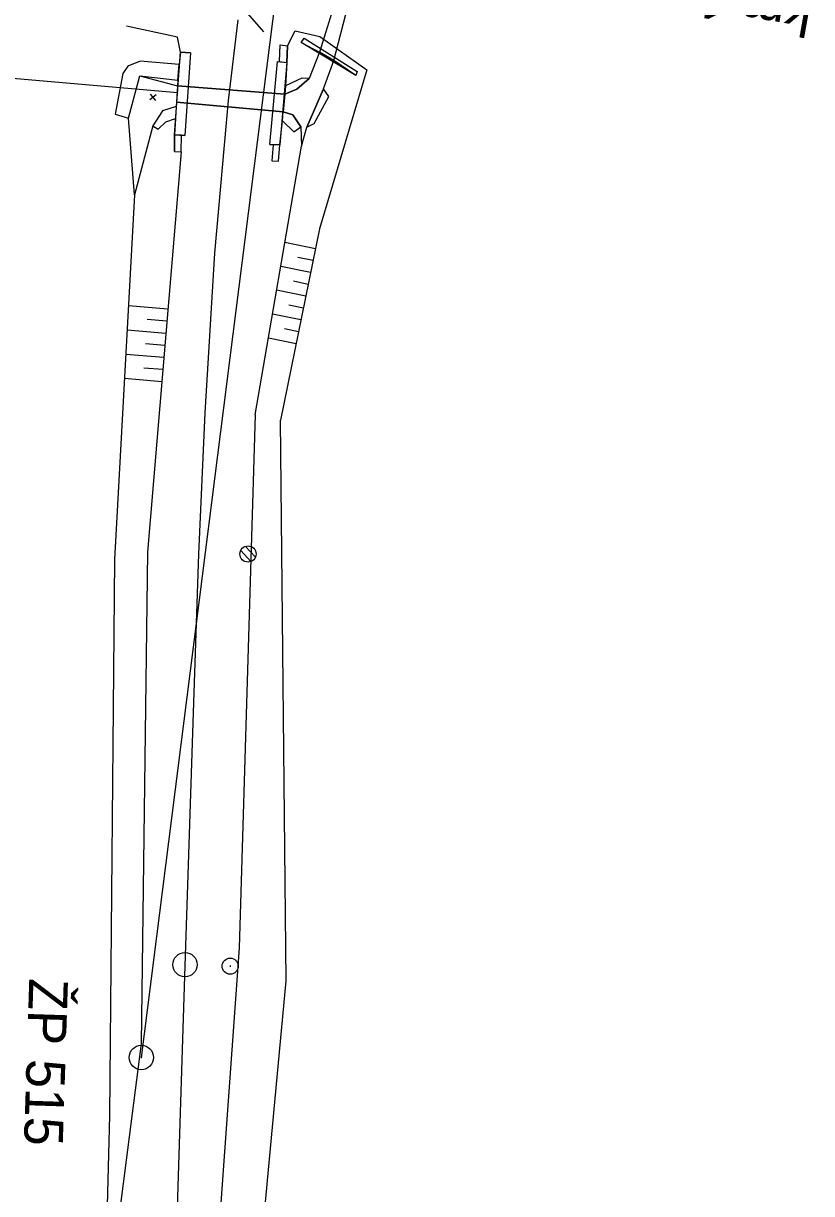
# Model space of a CAD drawing. Extents: x -738085 to -734426, y -1122197 to -1119748.
# Drawn here: x -735485.3 to -735436.6, y -1120600.6 to -1120528.2 of the extents above; entities that cross this region are included whole.
import ezdxf

# ---------------------------------------------------------------- set-up
doc = ezdxf.new("R2010")
doc.units = 0
for name, color, linetype in [('Vrstva 1', 7, 'Continuous'), ('Vrstva 11', 7, 'Continuous'), ('Vrstva 13', 7, 'Continuous'), ('Vrstva 19', 7, 'Continuous'), ('Vrstva 4', 7, 'Continuous'), ('Vrstva 48', 7, 'Continuous'), ('Vrstva 49', 7, 'Continuous'), ('Vrstva 63', 7, 'Continuous'), ('Vrstva 7', 7, 'Continuous'), ('Vrstva 9', 7, 'Continuous')]:
    doc.layers.add(name, color=color, linetype=linetype)

msp = doc.modelspace()

# ---------------------------------------------------------------- linework, layer by layer
at = {"layer": 'Vrstva 1'}
msp.add_lwpolyline([(-735472.033, -1120528.022), (-735472.637, -1120533.02), (-735473.481, -1120542.452), (-735474.077, -1120552.339), (-735474.468, -1120561.086), (-735474.782, -1120570.257), (-735475.334, -1120587.192), (-735475.897, -1120604.742)], dxfattribs=at)
msp.add_lwpolyline([(-735472.033, -1120528.022), (-735472.637, -1120533.02), (-735473.481, -1120542.452), (-735474.077, -1120552.339), (-735474.468, -1120561.086), (-735474.782, -1120570.257), (-735475.334, -1120587.192), (-735475.897, -1120604.742)], dxfattribs=at)
at = {"layer": 'Vrstva 11'}
for p, q in [((-735471.857, -1120560.849), (-735471.231, -1120561.533)), ((-735471.575, -1120560.601), (-735470.959, -1120561.275))]:
    msp.add_line(p, q, dxfattribs=at)
msp.add_circle((-735471.412, -1120561.07), 0.5, dxfattribs=at)
at = {"layer": 'Vrstva 13'}
for p, q in [((-735469.456, -1120530.61), (-735469.01, -1120530.674)), ((-735469.456, -1120530.61), (-735469.01, -1120530.674)), ((-735469.139, -1120532.633), (-735469.091, -1120532.115)), ((-735475.853, -1120533.392), (-735475.904, -1120534.129)), ((-735469.276, -1120534.274), (-735469.241, -1120533.724)), ((-735475.963, -1120536.178), (-735475.551, -1120536.186)), ((-735469.449, -1120535.765), (-735469.449, -1120535.765)), ((-735469.535, -1120536.761), (-735469.535, -1120536.761))]:
    msp.add_line(p, q, dxfattribs=at)
for points in [[(-735469.456, -1120530.61), (-735469.421, -1120529.58), (-735468.968, -1120529.627), (-735469.01, -1120530.674)], [(-735469.01, -1120530.674), (-735469.01, -1120530.674), (-735468.968, -1120529.627)], [(-735475.668, -1120530.787), (-735478.074, -1120530.581), (-735478.838, -1120530.892), (-735479.156, -1120531.352), (-735479.624, -1120533.867), (-735478.811, -1120534.119), (-735478.105, -1120531.488), (-735475.752, -1120531.75), (-735475.668, -1120530.787)], [(-735469.139, -1120532.633), (-735468.384, -1120532.305), (-735467.64, -1120531.662), (-735468.091, -1120531.635), (-735469.091, -1120532.115)], [(-735466.736, -1120532.288), (-735467.783, -1120534.657), (-735467.328, -1120534.443), (-735466.42, -1120532.761), (-735466.736, -1120532.288)], [(-735475.853, -1120533.392), (-735476.707, -1120533.65), (-735477.299, -1120534.592), (-735476.972, -1120534.792), (-735476.496, -1120534.327), (-735475.904, -1120534.129)], [(-735469.276, -1120534.274), (-735468.579, -1120534.96), (-735468.149, -1120534.642), (-735468.648, -1120533.901), (-735469.241, -1120533.724)], [(-735475.516, -1120535.164), (-735475.963, -1120535.13), (-735475.963, -1120536.178), (-735475.551, -1120536.186), (-735475.516, -1120535.164)], [(-735475.963, -1120536.178), (-735475.963, -1120536.178), (-735475.963, -1120535.13), (-735475.963, -1120535.13)], [(-735469.849, -1120535.753), (-735469.935, -1120536.75), (-735469.535, -1120536.761), (-735469.449, -1120535.765), (-735469.849, -1120535.753)], [(-735469.935, -1120536.75), (-735469.535, -1120536.761), (-735469.449, -1120535.765)]]:
    msp.add_lwpolyline(points, dxfattribs=at)
at = {"layer": 'Vrstva 19'}
for p, q in [((-735461.122, -1120511.205), (-735466.99, -1120530.023)), ((-735466.103, -1120530.55), (-735461.122, -1120511.205)), ((-735475.771, -1120532.55), (-735515.222, -1120529.126)), ((-735468.122, -1120529.424), (-735466.99, -1120530.023)), ((-735464.735, -1120531.469), (-735466.103, -1120530.55)), ((-735469.139, -1120532.633), (-735475.773, -1120532.099)), ((-735475.773, -1120532.099), (-735469.139, -1120532.633)), ((-735475.837, -1120533.127), (-735469.241, -1120533.724)), ((-735469.241, -1120533.724), (-735475.837, -1120533.127)), ((-735475.963, -1120535.13), (-735475.313, -1120535.18))]:
    msp.add_line(p, q, dxfattribs=at)
for points in [[(-735468.122, -1120529.424), (-735467.934, -1120529.164), (-735464.66, -1120531.219), (-735464.735, -1120531.469), (-735468.122, -1120529.424)], [(-735475.313, -1120535.18), (-735475.963, -1120535.13), (-735475.583, -1120530.02), (-735474.968, -1120530.061), (-735475.313, -1120535.18)], [(-735475.313, -1120535.18), (-735475.963, -1120535.13), (-735475.583, -1120530.02), (-735474.968, -1120530.061), (-735475.313, -1120535.18)], [(-735475.583, -1120530.02), (-735475.668, -1120530.787), (-735475.752, -1120531.75)], [(-735474.968, -1120530.061), (-735475.583, -1120530.02), (-735475.583, -1120530.02)], [(-735474.968, -1120530.061), (-735474.968, -1120530.061), (-735475.313, -1120535.18), (-735475.313, -1120535.18)], [(-735466.99, -1120530.023), (-735466.99, -1120530.023), (-735466.103, -1120530.55), (-735466.103, -1120530.55)], [(-735469.595, -1120530.603), (-735469.01, -1120530.674), (-735469.449, -1120535.765), (-735470.068, -1120535.747), (-735469.595, -1120530.603)], [(-735470.068, -1120535.747), (-735470.068, -1120535.747), (-735469.595, -1120530.603), (-735469.595, -1120530.603)], [(-735469.595, -1120530.603), (-735469.01, -1120530.674), (-735469.01, -1120530.674)], [(-735469.01, -1120530.674), (-735469.091, -1120532.115), (-735469.139, -1120532.633)], [(-735469.01, -1120530.674), (-735469.091, -1120532.115), (-735469.139, -1120532.633)], [(-735475.752, -1120531.75), (-735475.773, -1120532.099), (-735475.773, -1120532.099), (-735475.837, -1120533.127), (-735475.837, -1120533.127), (-735475.853, -1120533.392)], [(-735469.241, -1120533.724), (-735469.241, -1120533.724), (-735469.139, -1120532.633), (-735469.139, -1120532.633)], [(-735475.853, -1120533.392), (-735475.904, -1120534.129), (-735475.963, -1120535.13), (-735475.963, -1120535.13)], [(-735469.449, -1120535.765), (-735469.276, -1120534.274), (-735469.241, -1120533.724)], [(-735470.068, -1120535.747), (-735469.449, -1120535.765), (-735469.449, -1120535.765)]]:
    msp.add_lwpolyline(points, dxfattribs=at)
at = {"layer": 'Vrstva 4'}
msp.add_line((-735473.474, -1120525.286), (-735470.457, -1120528.771), dxfattribs=at)
at = {"layer": 'Vrstva 48'}
for p, q in [((-735467.238, -1120542.185), (-735469.129, -1120541.797)), ((-735467.388, -1120542.919), (-735468.322, -1120542.728)), ((-735467.538, -1120543.654), (-735469.385, -1120543.276)), ((-735467.689, -1120544.389), (-735468.601, -1120544.202)), ((-735467.839, -1120545.124), (-735469.641, -1120544.755)), ((-735476.371, -1120545.927), (-735478.808, -1120545.722)), ((-735467.99, -1120545.858), (-735468.879, -1120545.676)), ((-735468.14, -1120546.593), (-735469.897, -1120546.234)), ((-735476.434, -1120546.675), (-735477.642, -1120546.573)), ((-735468.29, -1120547.328), (-735469.158, -1120547.15)), ((-735476.497, -1120547.422), (-735478.891, -1120547.221)), ((-735468.441, -1120548.063), (-735470.153, -1120547.712)), ((-735476.56, -1120548.17), (-735477.746, -1120548.07)), ((-735476.623, -1120548.917), (-735478.974, -1120548.719)), ((-735476.686, -1120549.664), (-735477.851, -1120549.566)), ((-735476.749, -1120550.412), (-735479.057, -1120550.217))]:
    msp.add_line(p, q, dxfattribs=at)
at = {"layer": 'Vrstva 49'}
for p, q in [((-735477.102, -1120532.656), (-735477.486, -1120532.976)), ((-735477.454, -1120532.624), (-735477.134, -1120533.008)), ((-735475.853, -1120533.392), (-735475.904, -1120534.129)), ((-735475.837, -1120533.127), (-735475.853, -1120533.392)), ((-735475.904, -1120534.129), (-735475.963, -1120535.13)), ((-735475.963, -1120535.13), (-735475.963, -1120536.178)), ((-735475.551, -1120536.186), (-735477.636, -1120560.946)), ((-735475.963, -1120536.178), (-735475.551, -1120536.186)), ((-735469.044, -1120587.475), (-735469.407, -1120552.783)), ((-735477.636, -1120560.946), (-735478.023, -1120591.352)), ((-735471.118, -1120609.586), (-735469.044, -1120587.475)), ((-735478.023, -1120591.352), (-735480.326, -1120609.369))]:
    msp.add_line(p, q, dxfattribs=at)
for points in [[(-735475.583, -1120530.02), (-735475.776, -1120529.103), (-735478.93, -1120528.417)], [(-735468.968, -1120529.627), (-735468.491, -1120528.7), (-735466.967, -1120529.048), (-735464.056, -1120531.115), (-735466.984, -1120540.946), (-735469.407, -1120552.783)], [(-735468.968, -1120529.627), (-735469.01, -1120530.674), (-735469.091, -1120532.115), (-735469.139, -1120532.633)], [(-735475.583, -1120530.02), (-735475.668, -1120530.787), (-735475.752, -1120531.75), (-735475.773, -1120532.099)], [(-735470.976, -1120552.466), (-735468.097, -1120535.838), (-735467.783, -1120534.657), (-735466.736, -1120532.288), (-735466.103, -1120530.55), (-735466.99, -1120530.023), (-735467.64, -1120531.662), (-735468.384, -1120532.305), (-735469.139, -1120532.633), (-735469.241, -1120533.724), (-735468.648, -1120533.901), (-735468.149, -1120534.642), (-735468.097, -1120535.838)], [(-735478.428, -1120538.858), (-735478.811, -1120534.119), (-735478.105, -1120531.488), (-735475.773, -1120532.099), (-735475.837, -1120533.127), (-735475.853, -1120533.392), (-735476.707, -1120533.65), (-735477.299, -1120534.592), (-735478.428, -1120538.858), (-735479.676, -1120561.404), (-735479.972, -1120595.794), (-735480.326, -1120609.369), (-735480.747, -1120645.682), (-735481.688, -1120680.003), (-735482.703, -1120712.117)], [(-735470.976, -1120552.466), (-735471.959, -1120585.424), (-735473.327, -1120604.361), (-735473.353, -1120605.161), (-735473.031, -1120608.368), (-735474.218, -1120645.204), (-735475.523, -1120670.013), (-735475.548, -1120670.812), (-735475.765, -1120680.557), (-735476.869, -1120711.77)]]:
    msp.add_lwpolyline(points, dxfattribs=at)
at = {"layer": 'Vrstva 63'}
for p, q in [((-735478.008, -1120592.215), (-735464.41, -1120485.077)), ((-735478.006, -1120592.165), (-735478.01, -1120592.265))]:
    msp.add_line(p, q, dxfattribs=at)
msp.add_circle((-735478.008, -1120592.215), 0.756, dxfattribs=at)
at = {"layer": 'Vrstva 7'}
msp.add_line((-735472.512, -1120586.516), (-735472.516, -1120586.616), dxfattribs=at)
for centre, radius in [((-735475.311, -1120586.475), 0.75), ((-735475.311, -1120586.475), 0.75), ((-735472.514, -1120586.566), 0.5)]:
    msp.add_circle(centre, radius, dxfattribs=at)

# ---------------------------------------------------------------- texts
at = {"layer": 'Vrstva 63'}
msp.add_text('ŽP 515', height=2.4, rotation=268.16259, dxfattribs=at).set_placement((-735484.939, -1120587.301))
at = {"layer": 'Vrstva 9'}
msp.add_text('km 1,632', height=2.5, rotation=169.86358, dxfattribs=at).set_placement((-735436.34, -1120526.61))

doc.saveas('drawing.dxf')
